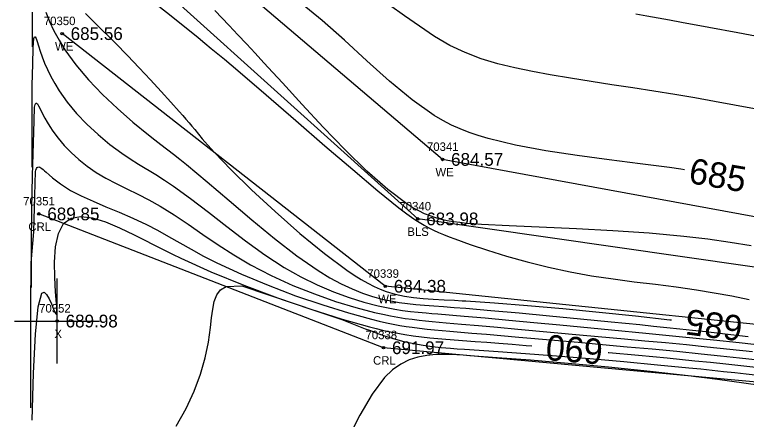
# Model space of a CAD drawing. Extents: x 1376587 to 1378239, y 1000335 to 1003031.
# Drawn here: x 1376924 to 1377010.1, y 1001512.6 to 1001560.2 of the extents above; entities that cross this region are included whole.
import ezdxf

# ---------------------------------------------------------------- set-up
doc = ezdxf.new("R2010")
doc.units = 0
for name, color, linetype in [('RD_DTM_BkLn1', 7, 'Continuous'), ('RD_DTM_BkLn_txCode', 7, 'Continuous'), ('RD_DTM_Major1', 7, 'Continuous'), ('RD_DTM_Major1_Lbl', 7, 'Continuous'), ('RD_DTM_Minor1', 7, 'Continuous'), ('RD_EX_H2O', 7, 'Continuous'), ('RD_EX_H2O_txCode', 7, 'Continuous'), ('RD_EX_Misc', 7, 'Continuous'), ('RD_EX_Misc_txCode', 7, 'Continuous'), ('RD_EX_TX_H2O_ELEV', 7, 'Continuous'), ('RD_EX_TX_Misc_ELEV', 7, 'Continuous'), ('RD_SMD_Locator', 7, 'Continuous')]:
    doc.layers.add(name, color=color, linetype=linetype)

msp = doc.modelspace()

# ---------------------------------------------------------------- linework, layer by layer
at = {"layer": 'RD_DTM_BkLn1'}
msp.add_lwpolyline([(1377322.969, 1001642.525), (1377293.605, 1001607.098), (1377249.432, 1001558.553), (1377170.427, 1001571.461), (1377111.377, 1001551.766), (1377054.733, 1001532.92), (1377033.73, 1001527.24), (1376971.435, 1001536.185), (1376926.988, 1001576.278)], dxfattribs=at)
at = {"layer": 'RD_DTM_Major1'}
for points in [[(1377002.826, 1001541.979), (1377002.414, 1001542.04), (1377001.047, 1001542.234), (1376997.627, 1001542.68), (1376993.971, 1001543.14), (1376990.215, 1001543.64), (1376986.494, 1001544.208), (1376982.945, 1001544.869), (1376979.703, 1001545.651), (1376978.56, 1001545.991), (1376977.471, 1001546.363), (1376976.421, 1001546.776), (1376975.399, 1001547.239), (1376974.391, 1001547.762), (1376973.384, 1001548.354), (1376970.778, 1001550.191), (1376968.126, 1001552.385), (1376965.455, 1001554.781), (1376962.794, 1001557.225), (1376960.172, 1001559.561), (1376957.617, 1001561.634)], [(1376932.335, 1001560.383), (1376933.473, 1001559.224), (1376935.858, 1001556.858), (1376937.275, 1001555.419), (1376938.662, 1001553.973), (1376939.992, 1001552.556), (1376941.237, 1001551.203), (1376942.37, 1001549.95), (1376943.362, 1001548.833), (1376943.774, 1001548.362), (1376944.156, 1001547.922), (1376944.514, 1001547.504), (1376944.855, 1001547.101), (1376945.187, 1001546.704), (1376946.076, 1001545.627), (1376946.384, 1001545.26), (1376946.723, 1001544.864), (1376947.104, 1001544.434), (1376947.535, 1001543.96), (1376949.443, 1001541.984), (1376951.877, 1001539.613), (1376954.647, 1001537.044), (1376957.566, 1001534.476), (1376960.444, 1001532.107), (1376963.093, 1001530.137), (1376963.959, 1001529.56), (1376964.777, 1001529.055), (1376965.555, 1001528.617), (1376966.301, 1001528.241), (1376967.02, 1001527.922), (1376967.721, 1001527.653), (1376968.794, 1001527.324), (1376969.863, 1001527.088), (1376970.949, 1001526.923), (1376972.075, 1001526.811), (1376973.265, 1001526.732), (1376974.54, 1001526.666), (1376975.768, 1001526.603), (1376976.647, 1001526.555), (1376977.107, 1001526.528), (1376980.479, 1001526.298), (1376984.331, 1001525.989), (1376988.49, 1001525.619), (1376992.785, 1001525.205), (1376997.044, 1001524.764), (1377001.093, 1001524.313), (1377001.316, 1001524.287)], [(1376926.048, 1001512.49), (1376926.206, 1001518.039), (1376926.433, 1001522.602), (1376926.754, 1001525.851), (1376927.191, 1001527.457), (1376927.461, 1001527.568), (1376927.751, 1001527.303), (1376928.043, 1001526.794), (1376928.321, 1001526.174), (1376928.567, 1001525.577), (1376928.766, 1001525.134), (1376928.804, 1001525.066), (1376928.839, 1001525.016), (1376928.87, 1001524.983), (1376928.896, 1001524.969), (1376928.919, 1001524.975), (1376928.937, 1001525.002), (1376928.947, 1001525.033), (1376928.955, 1001525.074), (1376928.961, 1001525.125), (1376928.965, 1001525.186), (1376928.967, 1001525.257), (1376928.967, 1001525.339), (1376928.965, 1001525.451), (1376928.961, 1001525.578), (1376928.944, 1001525.874), (1376928.92, 1001526.227), (1376928.816, 1001527.593), (1376928.719, 1001529.277), (1376928.694, 1001531.102), (1376928.812, 1001532.89), (1376929.137, 1001534.463), (1376929.739, 1001535.645), (1376930.626, 1001536.288), (1376931.782, 1001536.479), (1376933.155, 1001536.299), (1376934.695, 1001535.826), (1376936.35, 1001535.138), (1376938.07, 1001534.315), (1376938.932, 1001533.88), (1376940.695, 1001532.975), (1376941.613, 1001532.508), (1376942.564, 1001532.033), (1376943.557, 1001531.553), (1376947.09, 1001529.97), (1376950.949, 1001528.402), (1376954.938, 1001526.909), (1376958.865, 1001525.551), (1376962.533, 1001524.388), (1376965.749, 1001523.479), (1376966.533, 1001523.28), (1376967.274, 1001523.104), (1376967.975, 1001522.947), (1376968.643, 1001522.809), (1376969.283, 1001522.686), (1376969.901, 1001522.578), (1376970.91, 1001522.423), (1376971.885, 1001522.296), (1376972.84, 1001522.192), (1376973.792, 1001522.104), (1376974.755, 1001522.025), (1376978.206, 1001521.762), (1376979.551, 1001521.658), (1376980.989, 1001521.544), (1376982.531, 1001521.421), (1376984.19, 1001521.285), (1376984.862, 1001521.229)], [(1376993.829, 1001520.455), (1376993.926, 1001520.446), (1376997.395, 1001520.131), (1377000.801, 1001519.81), (1377004.038, 1001519.492), (1377005.904, 1001519.302), (1377007.699, 1001519.113), (1377009.456, 1001518.923), (1377011.209, 1001518.728)]]:
    msp.add_lwpolyline(points, dxfattribs=at)
at = {"layer": 'RD_DTM_Minor1'}
for points in [[(1376939.168, 1001562.696), (1376942.413, 1001560.084), (1376945.578, 1001557.537), (1376946.363, 1001556.896), (1376947.138, 1001556.258), (1376947.909, 1001555.619), (1376948.679, 1001554.975), (1376949.455, 1001554.323), (1376950.241, 1001553.657), (1376953.598, 1001550.783), (1376957.072, 1001547.778), (1376960.517, 1001544.796), (1376963.787, 1001541.987), (1376966.736, 1001539.504), (1376969.217, 1001537.499), (1376969.539, 1001537.249), (1376969.849, 1001537.013), (1376970.148, 1001536.79), (1376970.437, 1001536.579), (1376970.716, 1001536.379), (1376970.988, 1001536.191), (1376971.194, 1001536.053), (1376971.396, 1001535.921), (1376971.595, 1001535.794), (1376971.793, 1001535.673), (1376971.99, 1001535.555), (1376972.186, 1001535.442), (1376972.734, 1001535.144), (1376973.292, 1001534.867), (1376973.869, 1001534.603), (1376974.476, 1001534.347), (1376975.119, 1001534.092), (1376975.81, 1001533.83), (1376977.604, 1001533.184), (1376979.647, 1001532.498), (1376981.894, 1001531.801), (1376984.297, 1001531.123), (1376986.81, 1001530.491), (1376989.387, 1001529.936), (1376991.901, 1001529.489), (1376994.418, 1001529.116), (1376996.924, 1001528.789), (1376999.407, 1001528.484), (1377001.854, 1001528.174), (1377004.252, 1001527.834), (1377006.336, 1001527.491), (1377008.393, 1001527.113), (1377010.443, 1001526.709)], [(1377011.052, 1001549.156), (1377008.705, 1001549.588), (1377006.367, 1001550.014), (1377004.029, 1001550.429), (1377001.681, 1001550.828), (1376999.219, 1001551.225), (1376996.749, 1001551.608), (1376994.283, 1001551.984), (1376991.834, 1001552.361), (1376989.415, 1001552.745), (1376987.036, 1001553.145), (1376984.924, 1001553.531), (1376982.862, 1001553.96), (1376980.854, 1001554.459), (1376978.906, 1001555.051), (1376977.023, 1001555.762), (1376975.211, 1001556.618), (1376973.391, 1001557.677), (1376971.62, 1001558.862), (1376969.865, 1001560.112), (1376968.091, 1001561.367)], [(1376926.096, 1001556.445), (1376926.091, 1001558.526), (1376926.091, 1001560.509)], [(1376927.66, 1001560.513), (1376928.097, 1001559.444), (1376928.612, 1001558.345), (1376929.211, 1001557.227), (1376929.901, 1001556.103), (1376931.195, 1001554.315), (1376932.689, 1001552.555), (1376934.337, 1001550.838), (1376936.092, 1001549.178), (1376937.909, 1001547.59), (1376939.742, 1001546.087), (1376940.471, 1001545.511), (1376941.201, 1001544.943), (1376942.678, 1001543.797), (1376943.435, 1001543.203), (1376944.211, 1001542.583), (1376946.654, 1001540.559), (1376949.241, 1001538.354), (1376951.906, 1001536.087), (1376954.582, 1001533.876), (1376957.203, 1001531.84), (1376959.704, 1001530.098), (1376961.093, 1001529.253), (1376962.422, 1001528.538), (1376963.698, 1001527.942), (1376964.924, 1001527.452), (1376966.108, 1001527.057), (1376967.253, 1001526.744), (1376968.253, 1001526.524), (1376969.238, 1001526.351), (1376970.224, 1001526.216), (1376971.223, 1001526.109), (1376972.247, 1001526.02), (1376973.311, 1001525.94), (1376974.48, 1001525.857), (1376975.737, 1001525.766), (1376977.112, 1001525.661), (1376980.053, 1001525.418), (1376983.374, 1001525.122), (1376986.931, 1001524.79), (1376990.581, 1001524.438), (1376994.18, 1001524.082), (1376997.584, 1001523.74), (1376999.194, 1001523.576), (1377000.746, 1001523.416), (1377002.268, 1001523.256), (1377003.787, 1001523.093), (1377005.333, 1001522.923), (1377006.934, 1001522.742), (1377010.331, 1001522.346)], [(1377010.683, 1001533.002), (1377008.194, 1001533.419), (1377005.563, 1001533.798), (1377002.763, 1001534.131), (1376998.67, 1001534.497), (1376994.39, 1001534.779), (1376990.1, 1001535), (1376982.205, 1001535.352), (1376978.956, 1001535.529), (1376978.034, 1001535.593), (1376977.177, 1001535.665), (1376976.376, 1001535.75), (1376975.622, 1001535.853), (1376974.904, 1001535.978), (1376974.212, 1001536.13), (1376973.543, 1001536.313), (1376972.882, 1001536.534), (1376972.221, 1001536.8), (1376971.552, 1001537.119), (1376970.866, 1001537.498), (1376970.154, 1001537.944), (1376967.897, 1001539.643), (1376965.444, 1001541.82), (1376962.888, 1001544.319), (1376960.319, 1001546.984), (1376957.831, 1001549.659), (1376955.515, 1001552.188), (1376954.39, 1001553.416), (1376953.321, 1001554.579), (1376952.288, 1001555.697), (1376951.273, 1001556.788), (1376950.258, 1001557.873), (1376949.224, 1001558.969), (1376947.549, 1001560.73)], [(1377012.644, 1001557.423), (1377009.113, 1001558.075), (1377005.68, 1001558.716), (1377002.468, 1001559.312), (1377001.063, 1001559.569), (1376999.714, 1001559.814), (1376998.4, 1001560.052), (1376997.098, 1001560.287)], [(1376926.033, 1001542.271), (1376926.039, 1001545.7), (1376926.05, 1001548.973), (1376926.072, 1001551.936), (1376926.123, 1001554.419), (1376926.175, 1001556.312), (1376926.265, 1001557.41), (1376926.327, 1001557.634), (1376926.405, 1001557.63), (1376926.505, 1001557.428), (1376926.632, 1001557.058), (1376926.794, 1001556.551), (1376926.997, 1001555.938), (1376927.236, 1001555.269), (1376927.523, 1001554.542), (1376927.862, 1001553.767), (1376928.255, 1001552.957), (1376928.708, 1001552.125), (1376929.223, 1001551.282), (1376930.181, 1001549.937), (1376931.283, 1001548.615), (1376932.504, 1001547.333), (1376933.817, 1001546.11), (1376935.196, 1001544.965), (1376936.615, 1001543.916), (1376937.589, 1001543.263), (1376938.574, 1001542.643), (1376940.59, 1001541.411), (1376941.631, 1001540.758), (1376942.699, 1001540.052), (1376944.704, 1001538.607), (1376946.795, 1001536.998), (1376948.959, 1001535.301), (1376951.18, 1001533.595), (1376953.442, 1001531.957), (1376955.731, 1001530.464), (1376957.677, 1001529.362), (1376959.608, 1001528.411), (1376961.504, 1001527.604), (1376963.342, 1001526.932), (1376965.1, 1001526.386), (1376966.757, 1001525.959), (1376967.76, 1001525.743), (1376968.723, 1001525.566), (1376969.658, 1001525.421), (1376970.577, 1001525.301), (1376971.49, 1001525.2), (1376972.409, 1001525.112), (1376973.091, 1001525.051), (1376973.789, 1001524.992), (1376976.891, 1001524.738), (1376979.373, 1001524.523), (1376982.14, 1001524.272), (1376985.102, 1001523.997), (1376988.167, 1001523.707), (1376994.241, 1001523.128), (1376998.276, 1001522.743), (1377000.235, 1001522.554), (1377002.195, 1001522.36), (1377004.183, 1001522.159), (1377006.229, 1001521.944), (1377009.252, 1001521.616), (1377012.381, 1001521.266)], [(1376925.971, 1001528.098), (1376925.983, 1001532.849), (1376926.004, 1001537.393), (1376926.088, 1001541.244), (1376926.27, 1001547.745), (1376926.341, 1001549.341), (1376926.405, 1001549.646), (1376926.479, 1001549.799), (1376926.567, 1001549.817), (1376926.673, 1001549.717), (1376926.8, 1001549.515), (1376926.952, 1001549.228), (1376927.326, 1001548.486), (1376927.559, 1001548.043), (1376927.826, 1001547.563), (1376928.129, 1001547.058), (1376928.47, 1001546.535), (1376929.1, 1001545.685), (1376929.828, 1001544.831), (1376930.646, 1001543.987), (1376931.547, 1001543.169), (1376932.524, 1001542.391), (1376933.569, 1001541.667), (1376934.722, 1001540.979), (1376935.93, 1001540.339), (1376937.183, 1001539.718), (1376938.471, 1001539.088), (1376939.783, 1001538.421), (1376941.11, 1001537.691), (1376942.758, 1001536.673), (1376944.431, 1001535.552), (1376946.148, 1001534.364), (1376947.927, 1001533.147), (1376949.786, 1001531.939), (1376951.745, 1001530.776), (1376954.185, 1001529.508), (1376956.718, 1001528.362), (1376959.271, 1001527.347), (1376961.772, 1001526.472), (1376964.149, 1001525.745), (1376966.33, 1001525.173), (1376967.307, 1001524.952), (1376968.229, 1001524.766), (1376969.109, 1001524.609), (1376969.955, 1001524.476), (1376970.778, 1001524.364), (1376971.589, 1001524.266), (1376972.365, 1001524.182), (1376973.149, 1001524.105), (1376973.951, 1001524.032), (1376974.781, 1001523.96), (1376976.564, 1001523.809), (1376978.598, 1001523.633), (1376980.83, 1001523.434), (1376983.217, 1001523.218), (1376990.883, 1001522.517), (1376995.749, 1001522.072), (1376998.177, 1001521.848), (1377000.608, 1001521.618), (1377003.05, 1001521.381), (1377005.508, 1001521.133), (1377008.168, 1001520.855), (1377010.839, 1001520.565)], [(1376925.909, 1001513.924), (1376925.9, 1001519.958), (1376925.905, 1001525.741), (1376925.94, 1001531.024), (1376926.239, 1001534.675), (1376926.358, 1001538.927), (1376926.437, 1001541.749), (1376926.488, 1001541.923), (1376926.559, 1001542.103), (1376926.638, 1001542.223), (1376926.728, 1001542.289), (1376926.829, 1001542.306), (1376926.939, 1001542.28), (1376927.061, 1001542.217), (1376927.199, 1001542.12), (1376927.352, 1001541.996), (1376927.522, 1001541.846), (1376927.711, 1001541.677), (1376928.054, 1001541.373), (1376928.449, 1001541.037), (1376928.898, 1001540.677), (1376929.402, 1001540.303), (1376929.962, 1001539.922), (1376930.579, 1001539.544), (1376931.821, 1001538.891), (1376933.213, 1001538.256), (1376934.715, 1001537.619), (1376936.289, 1001536.963), (1376937.897, 1001536.267), (1376939.501, 1001535.516), (1376940.801, 1001534.842), (1376942.098, 1001534.126), (1376943.417, 1001533.377), (1376944.785, 1001532.604), (1376946.226, 1001531.815), (1376947.768, 1001531.021), (1376950.673, 1001529.671), (1376953.812, 1001528.367), (1376957.049, 1001527.148), (1376960.246, 1001526.05), (1376963.268, 1001525.112), (1376965.977, 1001524.37), (1376966.885, 1001524.149), (1376967.739, 1001523.958), (1376968.546, 1001523.793), (1376969.315, 1001523.651), (1376970.054, 1001523.528), (1376970.772, 1001523.421), (1376971.653, 1001523.305), (1376972.526, 1001523.205), (1376973.402, 1001523.117), (1376974.295, 1001523.035), (1376975.216, 1001522.957), (1376977.783, 1001522.744), (1376979.511, 1001522.597), (1376983.311, 1001522.27), (1376987.525, 1001521.903), (1376990.295, 1001521.661), (1376993.161, 1001521.407), (1376996.083, 1001521.143), (1376999.021, 1001520.872), (1377001.934, 1001520.596), (1377004.782, 1001520.314), (1377007.058, 1001520.08), (1377009.284, 1001519.843), (1377011.482, 1001519.602)], [(1376943.012, 1001511.777), (1376944.196, 1001513.846), (1376945.137, 1001515.891), (1376945.864, 1001517.889), (1376946.405, 1001519.82), (1376946.791, 1001521.661), (1376947.049, 1001523.392), (1376947.177, 1001524.524), (1376947.307, 1001525.563), (1376947.49, 1001526.481), (1376947.778, 1001527.248), (1376948.22, 1001527.836), (1376948.867, 1001528.218), (1376950.732, 1001528.31), (1376959.776, 1001525.253), (1376962.48, 1001524.338), (1376965.254, 1001523.258), (1376965.855, 1001523.029), (1376966.432, 1001522.816), (1376966.989, 1001522.617), (1376967.526, 1001522.433), (1376968.045, 1001522.264), (1376968.546, 1001522.108), (1376969.796, 1001521.764), (1376970.964, 1001521.5), (1376972.072, 1001521.302), (1376973.143, 1001521.156), (1376974.202, 1001521.047), (1376975.27, 1001520.96), (1376976.092, 1001520.902), (1376976.945, 1001520.845), (1376979.813, 1001520.662), (1376980.913, 1001520.588), (1376984.121, 1001520.353), (1376987.767, 1001520.065), (1376991.681, 1001519.736), (1376995.693, 1001519.383), (1376999.634, 1001519.019), (1377003.334, 1001518.661), (1377004.736, 1001518.519), (1377006.092, 1001518.379), (1377007.423, 1001518.238), (1377008.75, 1001518.095), (1377010.094, 1001517.947), (1377015.075, 1001517.393)], [(1377011.508, 1001516.623), (1377006.727, 1001517.266), (1377005.185, 1001517.464), (1377004.148, 1001517.593), (1377003.627, 1001517.657), (1376998.786, 1001518.21), (1376993.899, 1001518.712), (1376989.15, 1001519.157), (1376984.72, 1001519.538), (1376980.795, 1001519.848), (1376977.557, 1001520.081), (1376976.774, 1001520.133), (1376976.053, 1001520.175), (1376975.382, 1001520.206), (1376974.751, 1001520.222), (1376974.148, 1001520.223), (1376973.564, 1001520.205), (1376972.496, 1001520.111), (1376971.452, 1001519.915), (1376970.434, 1001519.586), (1376969.441, 1001519.093), (1376968.474, 1001518.407), (1376967.535, 1001517.496), (1376966.077, 1001515.539), (1376964.634, 1001513.073), (1376963.151, 1001510.242)]]:
    msp.add_lwpolyline(points, dxfattribs=at)
at = {"layer": 'RD_EX_H2O'}
for points in [[(1377396.047, 1001693.167), (1377388.971, 1001691.891), (1377383.547, 1001681.612), (1377370.954, 1001666.151), (1377345.792, 1001650.036), (1377349.116, 1001628.131), (1377334.126, 1001625.317), (1377311.323, 1001589.505), (1377259.373, 1001541.156), (1377186.141, 1001542.199), (1377119.382, 1001530.527), (1377065.136, 1001518.284), (1377035.175, 1001514.747), (1376967.402, 1001521.021), (1376926.832, 1001536.774)], [(1377334.456, 1001660.576), (1377318.223, 1001649.936), (1377286.502, 1001611.675), (1377286.502, 1001611.675), (1377237.873, 1001575.182), (1377169.705, 1001581.472), (1377109.998, 1001563.579), (1377053.341, 1001538.726), (1377032.875, 1001532.424), (1376974.355, 1001543.191), (1376926.217, 1001584.14)], [(1377346.874, 1001651.39), (1377329.206, 1001632.325), (1377301.199, 1001598.995), (1377255.164, 1001549.418), (1377172.114, 1001555.099), (1377120.453, 1001543.089), (1377120.453, 1001543.089), (1377055.21, 1001526.728), (1377035.209, 1001521.298), (1376967.617, 1001528.254), (1376929.582, 1001558.001)]]:
    msp.add_lwpolyline(points, dxfattribs=at)
at = {"layer": 'RD_EX_Misc'}
for p, q in [((1376928.989, 1001519.161), (1376928.989, 1001529.161)), ((1376923.989, 1001524.161), (1376933.989, 1001524.161))]:
    msp.add_line(p, q, dxfattribs=at)
at = {"layer": 'RD_SMD_Locator'}
for centre in [(1376929.582, 1001558.001), (1376974.355, 1001543.191), (1376926.832, 1001536.774), (1376971.435, 1001536.185), (1376967.617, 1001528.254), (1376928.989, 1001524.161), (1376967.402, 1001521.021)]:
    msp.add_circle(centre, 0.15, dxfattribs=at)

# ---------------------------------------------------------------- texts
at = {"layer": 'RD_DTM_BkLn_txCode'}
for s, p in [('70340', (1376969.278, 1001537.185)), ('BLS', (1376970.207, 1001534.185))]:
    msp.add_text(s, height=1, dxfattribs=at).set_placement(p)
at = {"layer": 'RD_DTM_Major1_Lbl'}
for s, rotation, p in [('685', 350.22721, (1377003.195, 1001540.436)), ('685', 172.73413, (1377009.815, 1001524.738)), ('690', 175.06698, (1376993.335, 1001522.01))]:
    msp.add_text(s, height=3, rotation=rotation, dxfattribs=at).set_placement(p)
at = {"layer": 'RD_EX_H2O_txCode'}
for s, p in [('70350', (1376927.425, 1001559.001)), ('WE', (1376928.743, 1001556.001)), ('70341', (1376972.52, 1001544.191)), ('WE', (1376973.516, 1001541.191)), ('70351', (1376924.997, 1001537.774)), ('CRL', (1376925.604, 1001534.774)), ('70339', (1376965.499, 1001529.254)), ('WE', (1376966.778, 1001526.254)), ('70338', (1376965.284, 1001522.021)), ('CRL', (1376966.174, 1001519.021))]:
    msp.add_text(s, height=1, dxfattribs=at).set_placement(p)
at = {"layer": 'RD_EX_Misc_txCode'}
for s, p in [('70352', (1376926.871, 1001525.161)), ('X', (1376928.674, 1001522.161))]:
    msp.add_text(s, height=1, dxfattribs=at).set_placement(p)
at = {"layer": 'RD_EX_TX_H2O_ELEV'}
for s, p in [('685.56', (1376930.582, 1001557.251)), ('684.57', (1376975.355, 1001542.441)), ('689.85', (1376927.832, 1001536.024)), ('684.38', (1376968.617, 1001527.504)), ('691.97', (1376968.402, 1001520.271))]:
    msp.add_text(s, height=1.5, dxfattribs=at).set_placement(p)
at = {"layer": 'RD_EX_TX_Misc_ELEV'}
for s, p in [('683.98', (1376972.435, 1001535.435)), ('689.98', (1376929.989, 1001523.411))]:
    msp.add_text(s, height=1.5, dxfattribs=at).set_placement(p)

doc.saveas('drawing.dxf')
